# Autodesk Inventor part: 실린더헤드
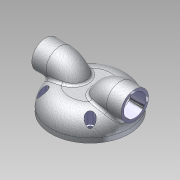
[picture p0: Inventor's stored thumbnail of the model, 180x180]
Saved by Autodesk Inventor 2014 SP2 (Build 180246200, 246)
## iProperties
Manager: KYOUNG IL JANG
Company: 한국ATC센터
Created: 2012-10
Part Number: 실린더헤드
Document SubType Name: Modeling
Density: 1 g/cm^3
Checked By: KYOUNG IL JANG
Vendor: CBT Solutions
Designer: KYOUNG IL JANG
Material: 일반
Appearance: _시험_알루미늄 표면거칠기
Author: KYOUNG IL JANG
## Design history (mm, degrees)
sketch "스케치1"
  geometry: C1 r 42.5 at (0, 0); 1 further point
  constraints: 1 centre point, 1 coincident
  dimensions: "d0" = 85 diameter of C1
extrude "돌출1" new body sketch "스케치1" distance "d1" = 25; taper "d2" = 0 deg
fillet "모깎기1" dims "d3" = 20
sketch "스케치2"
  geometry: C1 r 30 at (0, 0); 1 further point
  constraints: 1 centre point, 1 coincident
  dimensions: "d4" = 60 diameter of C1
extrude "돌출2" join sketch "스케치2" distance "d5" = 5; taper "d6" = 0 deg
sketch "스케치3"
  geometry: L1 (-42.5, 0)-(42.5, 0) reference; L2 (-48.5, 30)-(-33, 30); L3 (-17.545, 18.141)-(-12.684, 0); A1 r 16 centre (-33, 14) between (-17.545, 18.141) and (-33, 30); 1 further point
  constraints: 4 end point, 2 point on circle, 2 tangent, 1 centre point, 1 parallel, 1 point on line
  dimensions: "d7" = 16 radius of A1; "d8" = 6 horizontal distance of L2.start L1.start; "d9" = 30 distance between parallel lines of L2 L1; "d11" = 105 deg angle of L3 L1; "d36" = 15.5 distance of L2.start L2.end
node "작업 평면1"
sketch "스케치4"
  geometry: C1 r 15 at (0, 0); C2 r 12 at (0, 0); 2 further points
  constraints: 2 centre point, 2 coincident
  dimensions: "d12" = 30 diameter of C1; "d13" = 3 radial gap between concentric circles of C2 C1
feature "스윕1" dims "d14" = 0
feature "스윕2" dims "d15" = 0
sketch "스케치5"
  geometry: L1 (30, -5)-(-30, -5) reference; L2 (0, -5)-(0, 10); L3 (0, 10)-(-10, 10); A1 r 15 centre (-10, -5) between (-10, 10) and (-25, -5); 1 further point
  constraints: 4 end point, 2 perpendicular, 2 point on circle, 1 centre point, 1 midpoint, 1 point on line, 1 tangent
  dimensions: "d16" = 15 distance of L2.start L2.end; "d17" = 15 radius of A1; "d18" = 5 distance of L1.end A1.end
revolve "회전1" sketch "스케치5" stored, may be unused: angle "d19" = 90 deg
fillet "모깎기2" dims "d20" = 3
node "작업 평면2"
sketch "스케치6"
  geometry: L1 (0, 0)-(36.25, 0); C1 r 4.75 at (25.633, 25.633); C2 r 2.75 at (25.633, 25.633); A1 r 36.25 centre (0, 0) between (25.633, 25.633) and (36.25, 0); 1 further point
  constraints: 3 centre point, 2 coincident, 2 end point, 2 point on circle, 1 horizontal
  dimensions: "d22" = 72.5 diameter of A1; "d23" = 5.5 diameter of C2; "d24" = 9.5 diameter of C1; "d37" = 45 deg dimension on point (0, 0) C1.centre L1.end
extrude "돌출3" cut sketch "스케치6" stored distance "d25" = 5; taper "d26" = 0 deg
extrude "돌출4" cut sketch "스케치6" stored distance "d27" = 5; taper "d28" = 0 deg
chamfer "모따기1" distance "d33" = 1; stored, may be unused: second distance "d34" = 2, angle "d35" = 45 deg
node "솔리드1"
mirror "대칭1"
pattern_circular "원형 패턴1" dims angle "d30" = 360 deg
